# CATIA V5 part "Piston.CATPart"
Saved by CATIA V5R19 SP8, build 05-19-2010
Part number: Piston
Publications: "r", "rp", "i", "e", "hp", "La", "A"
Bounding box of the stored display mesh (mm): x -30 to 30, y -30 to 30, z -20 to 30
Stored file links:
  C:\Users\ThinkMotion\Desktop\EU_thinkMotion\iao\IAO_MMS_Groupe3\evulliez\evulliez\evulliez\Mecanisme\Piston.CATPart
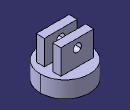
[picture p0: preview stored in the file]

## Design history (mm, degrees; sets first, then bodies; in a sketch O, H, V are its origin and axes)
Parameters
  r = 5 mm
  rp = 30 mm
  i = 10 mm
  e = 10 mm
  hp = 20 mm
  La = 40 mm
  A = 40 mm
Body1 (main body)
  Point1: (0, 0, 0)
  Line1: type PtDir, RefPoint Point1, Direction (0, 0, 1), Start -20 {= -hp}, End 20 {= A -hp}
  Plane1: type OffsetPt, RefPlane xy-plane, RefPoint vertex of Line1
  Sketch1 on Plane1, origin (0, 0, -20), H (1, 0, 0), V (0, 1, 0)
    circle A1 centre (0, 0) radius 30
    point P1 (0, 0)
    radius A1 = 30 {= rp}
    coincidence: O P1
  Pad1: profile Sketch1, direction (0, 0, 1), length 20 {= hp}
  Line2: type PtDir, RefPoint vertex of Line1, Direction (0, 1, 0), Start -15, End 15 {= (i +2*e )/2}
  Sketch2 on end face of Pad1, origin (0, 0, 0), H (1, 0, 0), V (0, 1, 0)
    line L1 (-20, -15) -> (20, -15)
    line L2 (20, -15) -> (20, -5)
    line L3 (20, -5) -> (-20, -5)
    line L4 (-20, -5) -> (-20, -15)
    reference projected point E1 (0, -15) from vertex of Line2
    point P5 (-20, 5)
    line L5 (-20, 5) -> (20, 5)
    line L6 (20, 5) -> (20, 15)
    line L7 (20, 15) -> (-20, 15)
    line L8 (-20, 15) -> (-20, 5)
    point P7 (20, 15)
    reference projected point E2 (0, 15) from vertex of Line2
    length L1 = 40 {= La}
    distance V L2 = 20 {= La /2}
    distance L1 L3 = 10 {= e}
    length L6 = 10 {= e}
    horizontal: L1 H, L3 H, L5 H, L7 H
    vertical: L2 V, L4 V, L6 V, L8 V
    coincidence: E1 L1, P5 L4, P7 L2, E2 L7
  Pad2: profile Sketch2, direction (0, 0, 1), length 30 {= A +r +5mm -hp}
  Sketch3 on face of Pad2 from Sketch2.L7, origin (0, 15, 20), H (1, 0, 0), V (0, 0, -1)
    point P1 (0, 0)
    reference projected point E1 (0, 0) from vertex of Line2
    coincidence: E1 P1
  Hole1: placed by Sketch3, at (0, 15, 20) direction (0, -1, 0), diameter 10 {= 2*r}, through (limit type 3)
